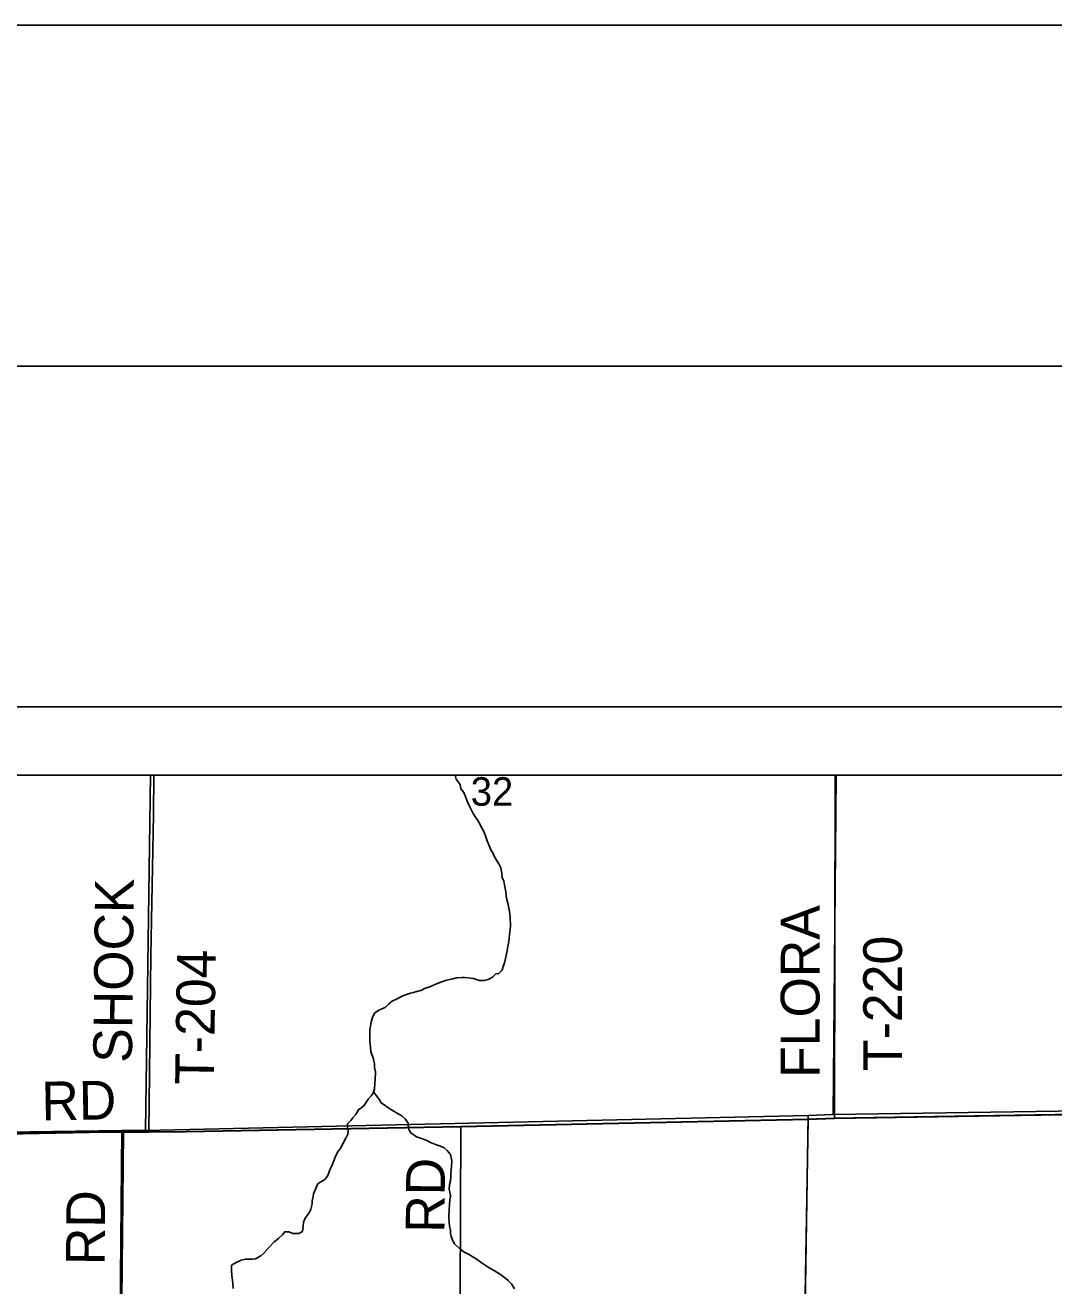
# Model space of a CAD drawing. Extents: x 0 to 34, y 0 to 22.
# Drawn here: x 3.392 to 4.9, y 20.151 to 22 of the extents above; entities that cross this region are included whole.
import ezdxf

# ---------------------------------------------------------------- set-up
doc = ezdxf.new("R2010")
doc.units = 0
for name, color, linetype in [('Default', 7, 'Continuous'), ('GM_X_County_Road', 7, 'Continuous'), ('GM_X_County_Road_Text', 7, 'Continuous'), ('GM_X_Minor_River', 7, 'Continuous'), ('GM_X_Section', 7, 'Continuous'), ('GM_X_Section_Text', 7, 'Continuous'), ('GM_X_Township', 7, 'Continuous'), ('GM_X_Township_Road', 7, 'Continuous'), ('GM_X_Township_Road_Text', 7, 'Continuous'), ('SH_Border', 7, 'Continuous'), ('SH_Cut_Line', 7, 'Continuous'), ('SH_Data', 7, 'Continuous')]:
    doc.layers.add(name, color=color, linetype=linetype)

msp = doc.modelspace()

# ---------------------------------------------------------------- linework, layer by layer
at = {"layer": 'Default'}
for points in [[(3.5755, 20.9), (2.6268, 20.9), (2.6217, 20.3656), (3.5337, 20.3786), (3.5682, 20.3787)], [(4.5809, 20.9), (3.5755, 20.9), (3.5682, 20.3787), (4.5401, 20.4008), (4.5765, 20.4024)], [(5.5805, 20.9), (4.5809, 20.9), (4.5765, 20.4024), (5.5347, 20.4166), (5.573, 20.4171)]]:
    msp.add_lwpolyline(points, close=True, dxfattribs=at)
at = {"layer": 'GM_X_County_Road'}
for p, q in [((4.5402, 20.3949), (4.5786, 20.3962)), ((4.5786, 20.3962), (5.2548, 20.4076)), ((3.5359, 20.3762), (3.5734, 20.3763))]:
    msp.add_line(p, q, dxfattribs=at)
for points in [[(3.5734, 20.3763), (3.6281, 20.3768), (4.0309, 20.3841), (4.5402, 20.3949)], [(2.8252, 20.371), (3.0357, 20.3712), (3.3911, 20.375), (3.494, 20.3761), (3.5359, 20.3762)]]:
    msp.add_lwpolyline(points, dxfattribs=at)
at = {"layer": 'GM_X_Minor_River'}
for points in [[(4.0224, 20.9), (4.0241, 20.8942), (4.0297, 20.8862), (4.0307, 20.8797), (4.0352, 20.8743), (4.037, 20.8694), (4.0404, 20.861), (4.043, 20.8553), (4.0489, 20.8438), (4.0519, 20.8388), (4.0552, 20.8343), (4.0593, 20.8274)], [(4.0593, 20.8274), (4.0608, 20.8232), (4.0638, 20.8182), (4.0671, 20.811), (4.0693, 20.8034), (4.0719, 20.7976), (4.0745, 20.7904), (4.0778, 20.7862), (4.0797, 20.7812), (4.083, 20.7755), (4.0867, 20.7701), (4.0893, 20.764), (4.0911, 20.7564), (4.0914, 20.75), (4.094, 20.7443), (4.0958, 20.7336), (4.0969, 20.7294), (4.0972, 20.7226), (4.0983, 20.7176), (4.1001, 20.7104), (4.1023, 20.6998), (4.1033, 20.6921), (4.1033, 20.688), (4.1036, 20.6823), (4.1035, 20.6781), (4.1027, 20.6705), (4.1019, 20.6663), (4.1018, 20.6603), (4.101, 20.6561), (4.099, 20.6463), (4.0986, 20.6421), (4.0962, 20.6311), (4.0946, 20.6247), (4.093, 20.6194), (4.0914, 20.6137), (4.0864, 20.6092), (4.0822, 20.6085), (4.0773, 20.6036), (4.0719, 20.6006), (4.0654, 20.5988), (4.0579, 20.5989), (4.0492, 20.6016), (4.0408, 20.6029), (4.0367, 20.6033), (4.0325, 20.6033), (4.0245, 20.6026), (4.0192, 20.6012), (4.0097, 20.5994), (3.9998, 20.5957), (3.9918, 20.5924), (3.9853, 20.5894), (3.9777, 20.5872), (3.9735, 20.5846), (3.9663, 20.5828), (3.9613, 20.5813), (3.9567, 20.5802), (3.951, 20.578), (3.9457, 20.5762), (3.9354, 20.571), (3.9304, 20.5691), (3.9247, 20.5639), (3.9205, 20.5597), (3.9163, 20.5579), (3.9117, 20.5556), (3.9048, 20.5512), (3.901, 20.5448), (3.8994, 20.5376), (3.8973, 20.5262), (3.8972, 20.5103), (3.8982, 20.5004), (3.8989, 20.4943), (3.9007, 20.4893), (3.9025, 20.4832), (3.904, 20.4764), (3.9043, 20.4711), (3.9054, 20.465), (3.9052, 20.4532), (3.9044, 20.4479), (3.9039, 20.4396), (3.9023, 20.4335), (3.8993, 20.4294), (3.8947, 20.4249), (3.8923, 20.4207), (3.8885, 20.4147), (3.8808, 20.4091), (3.877, 20.4023), (3.8723, 20.3974), (3.8693, 20.3933), (3.8647, 20.3884), (3.8646, 20.3838), (3.8657, 20.3781), (3.8649, 20.3732), (3.8621, 20.3675), (3.8544, 20.3528), (3.8501, 20.3468), (3.847, 20.3407), (3.8424, 20.3294), (3.8404, 20.3252), (3.8388, 20.3211), (3.8373, 20.3165), (3.835, 20.312)], [(3.9029, 20.4357), (3.9113, 20.4239), (3.9139, 20.4193), (3.9279, 20.4097), (3.9324, 20.407), (3.9388, 20.4031), (3.9441, 20.4004), (3.949, 20.3958), (3.9534, 20.3897), (3.9541, 20.3813), (3.9574, 20.3752), (3.9657, 20.3694), (3.9718, 20.3675), (3.9797, 20.3644), (3.9865, 20.3612), (3.9937, 20.3581), (4.0008, 20.3558), (4.0061, 20.3531), (4.0106, 20.3492), (4.0155, 20.3435), (4.0166, 20.3393), (4.0173, 20.3336), (4.0172, 20.326), (4.0168, 20.3218), (4.0163, 20.315), (4.0163, 20.3101), (4.0154, 20.3051), (4.0142, 20.2995), (4.0138, 20.2922), (4.0152, 20.2862), (4.0156, 20.282), (4.0147, 20.2771), (4.0139, 20.2698), (4.0134, 20.263), (4.0133, 20.2528), (4.0136, 20.244), (4.0143, 20.2391), (4.0154, 20.2322), (4.0157, 20.2277), (4.0164, 20.2235), (4.0186, 20.2182), (4.0208, 20.2132), (4.0298, 20.2048), (4.0366, 20.1998), (4.043, 20.197), (4.0476, 20.1939), (4.0532, 20.1905), (4.0607, 20.1851), (4.0709, 20.1781), (4.0758, 20.1754), (4.0799, 20.1727), (4.0848, 20.17), (4.089, 20.1673), (4.095, 20.1631), (4.1003, 20.1588), (4.1051, 20.1538), (4.1092, 20.1466)], [(3.835, 20.312), (3.8311, 20.3071), (3.8246, 20.303), (3.8204, 20.3), (3.8177, 20.2925), (3.8149, 20.286), (3.8141, 20.2819), (3.8129, 20.2758), (3.8125, 20.2713), (3.8109, 20.2633), (3.8086, 20.2591), (3.8055, 20.2542), (3.8024, 20.2501), (3.8, 20.2441), (3.7996, 20.238), (3.7984, 20.2308), (3.7934, 20.2278), (3.7843, 20.2279), (3.7783, 20.2299), (3.7726, 20.2303), (3.7691, 20.2258), (3.7634, 20.2205), (3.7572, 20.2153), (3.7495, 20.2074), (3.7422, 20.1995), (3.7376, 20.195), (3.7296, 20.1905), (3.7251, 20.1902), (3.7198, 20.1899), (3.7148, 20.1899), (3.7087, 20.1885), (3.7004, 20.1848), (3.6942, 20.181), (3.6942, 20.1734), (3.6948, 20.1662), (3.6959, 20.159), (3.6962, 20.1541), (3.6969, 20.1468)]]:
    msp.add_lwpolyline(points, dxfattribs=at)
at = {"layer": 'GM_X_Section'}
for points in [[(5.5347, 20.4166), (5.5276, 19.4562), (4.5252, 19.4639), (4.5401, 20.4008), (4.5765, 20.4024)], [(4.5401, 20.4008), (4.5252, 19.4639), (3.5253, 19.4614), (3.5337, 20.3786), (3.5682, 20.3787)], [(3.5337, 20.3786), (3.5253, 19.4614), (2.5858, 19.465), (2.6217, 20.3656)]]:
    msp.add_lwpolyline(points, close=True, dxfattribs=at)
at = {"layer": 'GM_X_Township'}
msp.add_lwpolyline([(2.5093, 17.4289), (2.5256, 18.0846), (2.5616, 18.9348), (2.5619, 18.941), (2.5631, 18.9701), (2.6034, 19.9491), (2.6035, 19.9525), (2.6217, 20.3636), (2.6265, 20.3636), (2.7999, 20.363), (2.8069, 20.3629), (2.814, 20.3628), (2.8217, 20.3627), (3.5356, 20.3768), (3.5731, 20.3768), (3.6279, 20.3774), (4.0307, 20.3846), (4.54, 20.3955), (4.5784, 20.3968), (5.284, 20.4086)], dxfattribs=at)
at = {"layer": 'GM_X_Township_Road'}
for p, q in [((4.5786, 20.3962), (4.5798, 20.9)), ((4.5325, 19.963), (4.5402, 20.3949)), ((4.5402, 20.3949), (4.5786, 20.3962)), ((3.5359, 20.3762), (3.5734, 20.3763))]:
    msp.add_line(p, q, dxfattribs=at)
for points in [[(8.5676, 20.9), (2.6262, 20.9), (2.6255, 20.8483), (2.6258, 20.7122), (2.6258, 20.7117), (2.6259, 20.6863), (2.6259, 20.6758), (2.6254, 20.6074), (2.6224, 20.4009), (2.6222, 20.3879), (2.622, 20.3702), (2.6217, 20.3636), (2.6265, 20.3636), (2.7999, 20.363), (2.8069, 20.3629), (2.814, 20.3628), (2.8217, 20.3627), (3.5356, 20.3768), (3.5731, 20.3768), (3.6279, 20.3774), (4.0307, 20.3846), (4.54, 20.3955), (4.5784, 20.3968), (5.284, 20.4086)], [(3.5734, 20.3763), (3.5763, 20.6352), (3.58, 20.8423), (3.5807, 20.9)], [(4.0282, 19.9699), (4.0292, 20.0154), (4.0309, 20.3841)], [(3.5284, 19.619), (3.5292, 19.7152), (3.5303, 19.8391), (3.5333, 20.0814), (3.5359, 20.3762)]]:
    msp.add_lwpolyline(points, dxfattribs=at)
at = {"layer": 'SH_Border'}
msp.add_lwpolyline([(1.5, 21.5), (33.5, 21.5), (33.5, 0.5), (1.5, 0.5)], close=True, dxfattribs=at)
at = {"layer": 'SH_Cut_Line'}
msp.add_lwpolyline([(0, 0), (34, 0), (34, 22), (0, 22)], close=True, dxfattribs=at)
msp.add_lwpolyline([(8.9, 20.9), (2.1, 20.9), (2.1, 14.5206)], dxfattribs=at)
at = {"layer": 'SH_Data'}
for p, q in [((2, 21), (9, 21)), ((2.1, 20.9), (8.9, 20.9))]:
    msp.add_line(p, q, dxfattribs=at)

# ---------------------------------------------------------------- texts
at = {"layer": 'GM_X_County_Road_Text'}
msp.add_text('RD', height=0.05682, rotation=0.9872, dxfattribs=at).set_placement((3.4162, 20.3934))
at = {"layer": 'GM_X_Section_Text'}
msp.add_text('32', height=0.04186, rotation=0, dxfattribs=at).set_placement((4.0453, 20.8551))
at = {"layer": 'GM_X_Township_Road_Text'}
for s, rotation, p in [('SHOCK', 89.39, (3.5484, 20.4778)), ('FLORA', 90, (4.5567, 20.4559)), ('T-220', 90, (4.6777, 20.4659)), ('T-204', 89.1569, (3.6685, 20.4453)), ('RD', 89.5063, (4.0067, 20.2286)), ('RD', 89.5063, (3.5084, 20.1811))]:
    msp.add_text(s, height=0.05682, rotation=rotation, dxfattribs=at).set_placement(p)

doc.saveas('drawing.dxf')
